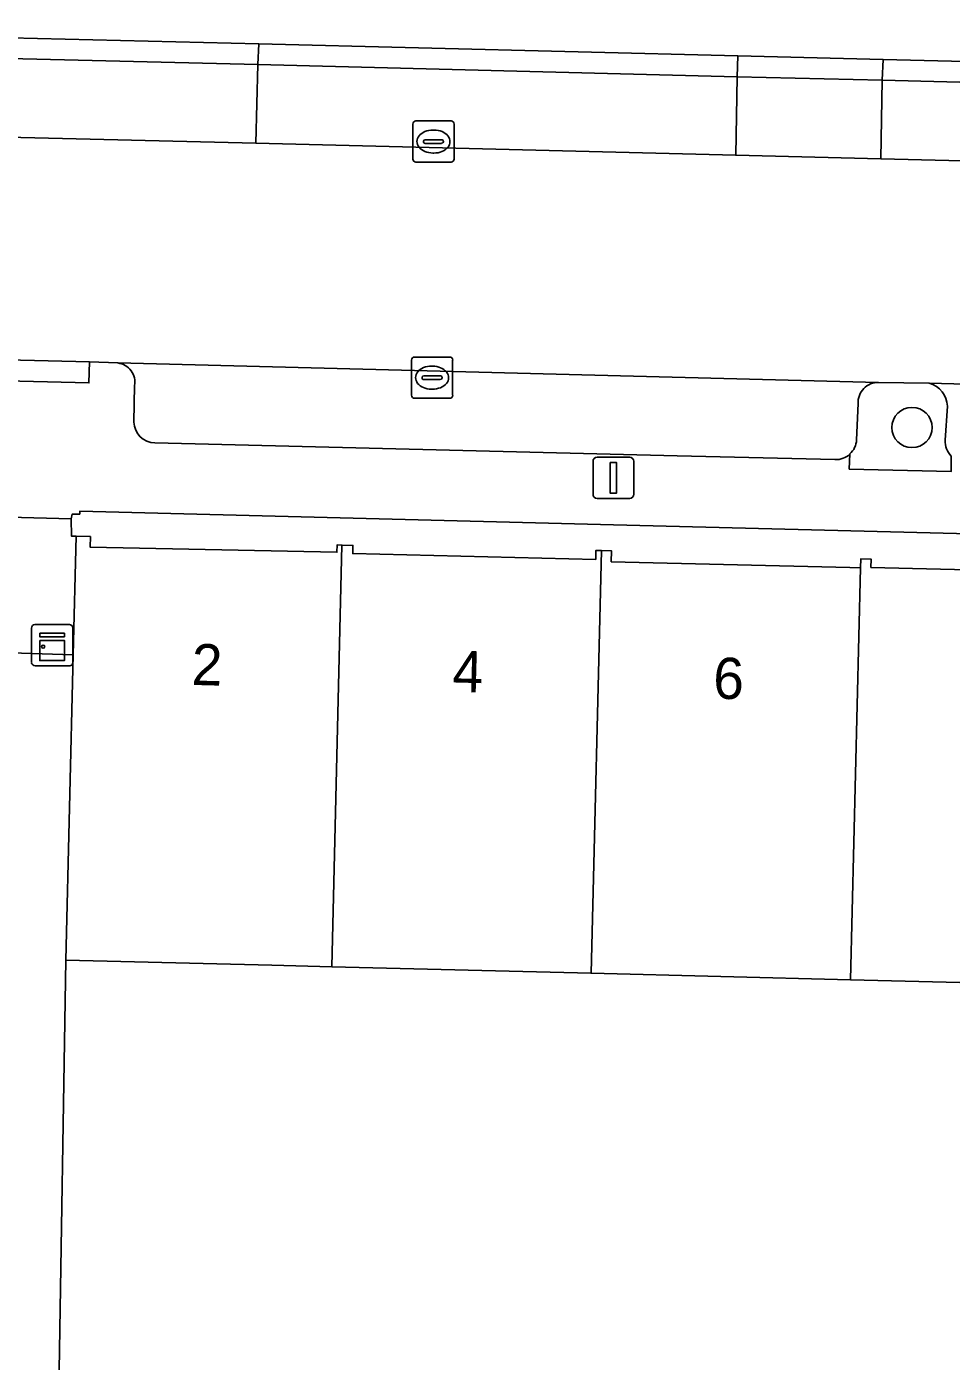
# Model space of a CAD drawing. Extents: x 162082 to 163401, y 388089 to 388636.
# Drawn here: x 162369.45 to 162391.89, y 388440.14 to 388472.55 of the extents above; entities that cross this region are included whole.
import ezdxf

# ---------------------------------------------------------------- set-up
doc = ezdxf.new("R2010")
doc.units = 0
for name, color, linetype in [('IMGEO_Berm_open', 7, 'Continuous'), ('IMGEO_Boom', 7, 'Continuous'), ('IMGEO_Erf', 7, 'Continuous'), ('IMGEO_Fietspad_gesloten', 7, 'Continuous'), ('IMGEO_Groenvoorziening', 7, 'Continuous'), ('IMGEO_Kast', 7, 'Continuous'), ('IMGEO_Kolk', 7, 'Continuous'), ('IMGEO_Lichtmast', 7, 'Continuous'), ('IMGEO_Pand', 7, 'Continuous'), ('IMGEO_Pand_nummerreeks', 7, 'Continuous'), ('IMGEO_Parkeervlak_open', 7, 'Continuous'), ('IMGEO_Rijbaan_lokaal_gesloten', 7, 'Continuous'), ('IMGEO_Rijbaan_lokaal_open', 7, 'Continuous'), ('IMGEO_Voetpad_open', 7, 'Continuous')]:
    doc.layers.add(name, color=color, linetype=linetype)

msp = doc.modelspace()

# ---------------------------------------------------------------- linework, layer by layer
at = {"layer": 'IMGEO_Berm_open'}
for points in [[(162386.708, 388471.847), (162375.078, 388472.135), (162375.054, 388471.636), (162386.691, 388471.334)], [(162401.837, 388471.472), (162390.238, 388471.759), (162390.215, 388471.253), (162401.824, 388470.956)]]:
    msp.add_lwpolyline(points, close=True, dxfattribs=at)
at = {"layer": 'IMGEO_Boom'}
msp.add_circle((162390.937, 388462.819), 0.489, dxfattribs=at)
at = {"layer": 'IMGEO_Erf'}
for points in [[(162433.966, 388459.183), (162383.691, 388460.456), (162370.734, 388460.784), (162370.734, 388460.717), (162370.655, 388460.714), (162370.546, 388460.711), (162370.521, 388460.602), (162370.536, 388460.18), (162370.644, 388460.18), (162370.99, 388460.172), (162370.984, 388459.916), (162376.976, 388459.791), (162376.982, 388459.966), (162377.097, 388459.963), (162377.365, 388459.957), (162377.36, 388459.757), (162383.26, 388459.614), (162383.265, 388459.833), (162383.396, 388459.83), (162383.643, 388459.824), (162383.636, 388459.56), (162389.43, 388459.416), (162389.687, 388459.409), (162389.692, 388459.628), (162389.944, 388459.622), (162389.939, 388459.421), (162395.682, 388459.278)], [(162433.427, 388437.851), (162433.687, 388448.306), (162427.233, 388448.467), (162420.935, 388448.623), (162420.878, 388446.285), (162418.504, 388446.407), (162418.62, 388448.681), (162414.638, 388448.78), (162408.34, 388448.937), (162402.042, 388449.094), (162395.743, 388449.25), (162389.445, 388449.407), (162383.147, 388449.564), (162376.849, 388449.721), (162375.393, 388449.757), (162370.394, 388449.881), (162370.224, 388439.424)]]:
    msp.add_lwpolyline(points, dxfattribs=at)
at = {"layer": 'IMGEO_Fietspad_gesloten'}
msp.add_lwpolyline([(162358.201, 388472.554), (162369.037, 388472.285), (162375.078, 388472.135), (162386.708, 388471.847), (162390.238, 388471.759), (162401.837, 388471.472), (162408.03, 388471.318), (162408.007, 388470.829), (162416.505, 388470.602), (162416.525, 388471.113), (162420.862, 388471.019), (162440.416, 388470.49), (162440.436, 388470.49), (162448.448, 388470.301), (162458.442, 388470.036), (162464.998, 388469.844), (162475.747, 388469.573), (162481.767, 388469.41), (162492.263, 388469.129), (162498.783, 388468.948), (162509.296, 388468.657)], dxfattribs=at)
at = {"layer": 'IMGEO_Groenvoorziening'}
for points in [[(162391.354, 388463.895), (162390.127, 388463.916)], [(162389.627, 388463.4), (162389.593, 388462.517)], [(162391.74, 388462.51), (162391.795, 388463.337)], [(162389.43, 388462.176), (162389.414, 388461.81), (162391.884, 388461.749), (162391.891, 388462.126)]]:
    msp.add_lwpolyline(points, dxfattribs=at)
for centre, radius, start, end in [((162390.122, 388463.42), 0.496, 89.4454, 182.359), ((162391.201, 388463.32), 0.595, 1.5906, 75.0496), ((162389.08, 388462.553), 0.514, 312.8768, 356.0271), ((162392.287, 388462.503), 0.547, 179.3135, 223.6188)]:
    msp.add_arc(centre, radius, start, end, dxfattribs=at)
at = {"layer": 'IMGEO_Kast'}
for p, q in [((162369.565, 388457.108), (162369.565, 388457.949)), ((162369.565, 388457.949), (162369.565, 388457.108)), ((162369.64, 388458.033), (162370.481, 388458.033)), ((162370.481, 388458.033), (162369.64, 388458.033)), ((162370.565, 388457.958), (162370.565, 388457.117)), ((162370.565, 388457.117), (162370.565, 388457.958)), ((162370.49, 388457.033), (162369.649, 388457.033)), ((162369.649, 388457.033), (162370.49, 388457.033))]:
    msp.add_line(p, q, dxfattribs=at)
for points in [[(162369.76, 388457.823), (162370.36, 388457.823), (162370.36, 388457.738), (162369.76, 388457.738), (162369.76, 388457.823)], [(162369.76, 388457.648), (162370.36, 388457.648), (162370.36, 388457.159), (162369.76, 388457.159), (162369.76, 388457.648)]]:
    msp.add_lwpolyline(points, dxfattribs=at)
msp.add_circle((162369.844, 388457.497), 0.0377, dxfattribs=at)
for centre, start, end in [((162369.643, 388457.955), 92.4484, 184.2845), ((162369.643, 388457.955), 92.4484, 184.2845), ((162370.487, 388457.955), 2.4484, 94.2845), ((162370.487, 388457.955), 2.4484, 94.2845), ((162369.643, 388457.111), 182.4484, 274.2845), ((162369.643, 388457.111), 182.4484, 274.2845), ((162370.487, 388457.111), 272.4484, 4.2845), ((162370.487, 388457.111), 272.4484, 4.2845)]:
    msp.add_arc(centre, 0.0779, start, end, dxfattribs=at)
at = {"layer": 'IMGEO_Kolk'}
for p, q in [((162378.894, 388470.264), (162379.746, 388470.264)), ((162378.819, 388469.338), (162378.819, 388470.19)), ((162379.307, 388470.044), (162379.332, 388470.044)), ((162379.82, 388470.19), (162379.82, 388469.338)), ((162379.078, 388469.758), (162379.078, 388469.77)), ((162379.516, 388469.721), (162379.118, 388469.721)), ((162379.121, 388469.807), (162379.519, 388469.807)), ((162379.562, 388469.77), (162379.562, 388469.758)), ((162379.746, 388469.264), (162378.894, 388469.264)), ((162379.33, 388469.484), (162379.305, 388469.484)), ((162378.785, 388463.604), (162378.785, 388464.456)), ((162378.86, 388464.53), (162379.712, 388464.53)), ((162379.786, 388464.456), (162379.786, 388463.604)), ((162379.087, 388464.073), (162379.485, 388464.073)), ((162379.273, 388464.31), (162379.298, 388464.31)), ((162379.044, 388464.024), (162379.044, 388464.036)), ((162379.482, 388463.987), (162379.084, 388463.987)), ((162379.296, 388463.75), (162379.271, 388463.75)), ((162379.528, 388464.036), (162379.528, 388464.024)), ((162379.712, 388463.53), (162378.86, 388463.53))]:
    msp.add_line(p, q, dxfattribs=at)
for points in [[(162378.894, 388470.264), (162379.746, 388470.264)], [(162378.819, 388469.338), (162378.819, 388470.19)], [(162379.82, 388470.19), (162379.82, 388469.338)], [(162379.746, 388469.264), (162378.894, 388469.264)], [(162378.785, 388463.604), (162378.785, 388464.456)], [(162378.86, 388464.53), (162379.712, 388464.53)], [(162379.786, 388464.456), (162379.786, 388463.604)], [(162379.712, 388463.53), (162378.86, 388463.53)]]:
    msp.add_lwpolyline(points, dxfattribs=at)
for centre, radius, start, end in [((162378.896, 388470.188), 0.0765, 91.552, 178.448), ((162378.896, 388470.188), 0.0765, 91.552, 178.448), ((162379.744, 388470.188), 0.0765, 1.552, 88.448), ((162379.744, 388470.188), 0.0765, 1.552, 88.448), ((162379.118, 388469.767), 0.0403, 85.8775, 175.7526), ((162379.115, 388469.757), 0.0366, 178.938, 274.7102), ((162379.519, 388469.764), 0.043, 264.8664, 352.4533), ((162379.523, 388469.769), 0.0386, 1.7309, 96.639), ((162378.896, 388469.34), 0.0765, 181.552, 268.448), ((162378.896, 388469.34), 0.0765, 181.552, 268.448), ((162379.744, 388469.34), 0.0765, 271.552, 358.448), ((162379.744, 388469.34), 0.0765, 271.552, 358.448), ((162378.862, 388464.454), 0.0765, 91.552, 178.448), ((162378.862, 388464.454), 0.0765, 91.552, 178.448), ((162379.71, 388464.454), 0.0765, 1.552, 88.448), ((162379.71, 388464.454), 0.0765, 1.552, 88.448), ((162379.084, 388464.033), 0.0403, 85.8775, 175.7526), ((162379.489, 388464.035), 0.0386, 1.7309, 96.639), ((162379.081, 388464.023), 0.0366, 178.938, 274.7102), ((162379.485, 388464.03), 0.043, 264.8664, 352.4533), ((162378.862, 388463.606), 0.0765, 181.552, 268.448), ((162378.862, 388463.606), 0.0765, 181.552, 268.448), ((162379.71, 388463.606), 0.0765, 271.552, 358.448), ((162379.71, 388463.606), 0.0765, 271.552, 358.448)]:
    msp.add_arc(centre, radius, start, end, dxfattribs=at)
for centre, major_axis, ratio, start_param, end_param in [((162379.306, 388469.764), (-0.387, 0.002), 0.722429, 4.712389, 7.853982), ((162379.331, 388469.764), (-0.39, 0.002), 0.717154, 1.570796, 4.712389), ((162379.272, 388464.03), (-0.387, 0.002), 0.722429, 4.712389, 7.853982), ((162379.297, 388464.03), (-0.39, 0.002), 0.717154, 1.570796, 4.712389)]:
    msp.add_ellipse(centre, major_axis=major_axis, ratio=ratio, start_param=start_param, end_param=end_param, dxfattribs=at)
at = {"layer": 'IMGEO_Lichtmast'}
for p, q in [((162383.193, 388461.198), (162383.193, 388461.998)), ((162383.193, 388461.998), (162383.193, 388461.198)), ((162383.293, 388462.098), (162384.083, 388462.098)), ((162384.083, 388462.098), (162383.293, 388462.098)), ((162384.183, 388461.998), (162384.183, 388461.198)), ((162384.183, 388461.198), (162384.183, 388461.998)), ((162384.083, 388461.098), (162383.293, 388461.098)), ((162383.293, 388461.098), (162384.083, 388461.098))]:
    msp.add_line(p, q, dxfattribs=at)
msp.add_lwpolyline([(162383.613, 388461.973), (162383.763, 388461.973), (162383.763, 388461.223), (162383.613, 388461.223), (162383.613, 388461.973)], dxfattribs=at)
for centre, start, end in [((162383.293, 388461.998), 90, 180), ((162383.293, 388461.998), 90, 180), ((162384.083, 388461.998), 0, 90), ((162384.083, 388461.998), 360, 90), ((162383.293, 388461.198), 180, 270), ((162383.293, 388461.198), 180, 270), ((162384.083, 388461.198), 270, 0), ((162384.083, 388461.198), 270, 0)]:
    msp.add_arc(centre, 0.1, start, end, dxfattribs=at)
at = {"layer": 'IMGEO_Pand'}
for points in [[(162376.849, 388449.721), (162377.097, 388459.963), (162376.982, 388459.966), (162376.976, 388459.791), (162370.984, 388459.916), (162370.99, 388460.172), (162370.644, 388460.18), (162370.574, 388457.3), (162370.394, 388449.881), (162375.393, 388449.757)], [(162383.396, 388459.83), (162383.265, 388459.833), (162383.26, 388459.614), (162377.36, 388459.757), (162377.365, 388459.957), (162377.097, 388459.963), (162376.849, 388449.721), (162383.147, 388449.564)], [(162389.687, 388459.409), (162389.43, 388459.416), (162383.636, 388459.56), (162383.643, 388459.824), (162383.396, 388459.83), (162383.147, 388449.564), (162389.445, 388449.407)], [(162395.986, 388459.271), (162395.682, 388459.278), (162389.939, 388459.421), (162389.944, 388459.622), (162389.692, 388459.628), (162389.687, 388459.409), (162389.445, 388449.407), (162395.743, 388449.25)]]:
    msp.add_lwpolyline(points, close=True, dxfattribs=at)
at = {"layer": 'IMGEO_Parkeervlak_open'}
msp.add_lwpolyline([(162386.691, 388471.334), (162375.054, 388471.636), (162375.01, 388469.723), (162386.66, 388469.431)], close=True, dxfattribs=at)
for points in [[(162401.824, 388470.956), (162390.215, 388471.253), (162390.18, 388469.346), (162402.728, 388469.034)], [(162390.127, 388463.916), (162371.659, 388464.386)], [(162372.065, 388463.838), (162372.047, 388462.949)], [(162420.621, 388463.13), (162408.184, 388463.445), (162391.354, 388463.895)], [(162389.593, 388462.517), (162389.627, 388463.4)], [(162391.795, 388463.337), (162391.74, 388462.51)], [(162372.557, 388462.447), (162385.239, 388462.134), (162389.067, 388462.04)]]:
    msp.add_lwpolyline(points, dxfattribs=at)
for centre, radius, start, end in [((162371.595, 388463.914), 0.477, 350.844, 82.2237), ((162390.122, 388463.42), 0.496, 89.4454, 182.359), ((162391.201, 388463.32), 0.595, 1.5906, 75.0496), ((162372.565, 388462.965), 0.518, 181.8053, 269.1005), ((162389.08, 388462.553), 0.514, 312.8768, 356.0271), ((162392.287, 388462.503), 0.547, 179.3135, 223.6188), ((162389.084, 388462.547), 0.508, 268.0986, 312.9789)]:
    msp.add_arc(centre, radius, start, end, dxfattribs=at)
at = {"layer": 'IMGEO_Rijbaan_lokaal_gesloten'}
for points in [[(162504.674, 388466.396), (162498.717, 388466.552), (162492.196, 388466.723), (162481.721, 388466.997), (162474.776, 388467.179), (162471.449, 388467.262), (162471.402, 388467.266), (162464.938, 388467.441), (162458.384, 388467.618), (162448.429, 388467.886), (162439.373, 388468.131), (162439.33, 388468.131), (162438.401, 388468.167), (162419.774, 388468.618), (162418.749, 388468.644), (162408.223, 388468.89), (162403.702, 388469.023), (162402.728, 388469.034), (162390.18, 388469.346), (162386.66, 388469.431), (162375.01, 388469.723), (162368.972, 388469.873), (162357.12, 388470.167), (162357.479, 388464.187)], [(162363.947, 388464.619), (162365.328, 388464.563), (162365.948, 388464.538), (162370.967, 388464.412), (162371.659, 388464.386), (162390.127, 388463.916), (162391.354, 388463.895), (162408.184, 388463.445), (162420.621, 388463.13), (162421.807, 388463.11), (162462.126, 388462.081), (162463.206, 388462.062), (162475.436, 388461.725), (162497.037, 388461.139)]]:
    msp.add_lwpolyline(points, dxfattribs=at)
at = {"layer": 'IMGEO_Rijbaan_lokaal_open'}
msp.add_lwpolyline([(162370.644, 388460.18), (162370.536, 388460.18), (162370.521, 388460.602), (162366.001, 388460.726), (162365.975, 388460.578), (162365.87, 388459.93), (162365.799, 388457.454), (162370.574, 388457.3)], close=True, dxfattribs=at)
msp.add_lwpolyline([(162370.224, 388439.424), (162370.394, 388449.881), (162370.574, 388457.3), (162365.799, 388457.454)], dxfattribs=at)
at = {"layer": 'IMGEO_Voetpad_open'}
for points in [[(162375.078, 388472.135), (162369.037, 388472.285), (162369.02, 388471.78), (162375.054, 388471.636)], [(162390.238, 388471.759), (162386.708, 388471.847), (162386.691, 388471.334), (162390.215, 388471.253)], [(162375.054, 388471.636), (162369.02, 388471.78), (162368.972, 388469.873), (162375.01, 388469.723)], [(162390.215, 388471.253), (162386.691, 388471.334), (162386.66, 388469.431), (162390.18, 388469.346)], [(162370.967, 388464.412), (162365.948, 388464.538), (162365.916, 388464.025), (162370.954, 388463.902)]]:
    msp.add_lwpolyline(points, close=True, dxfattribs=at)
for points in [[(162371.659, 388464.386), (162370.967, 388464.412), (162370.954, 388463.902), (162365.916, 388464.025), (162365.948, 388464.538), (162365.328, 388464.563), (162365.27, 388462.394), (162359.684, 388462.54), (162359.741, 388464.48), (162359.611, 388464.465)], [(162372.047, 388462.949), (162372.065, 388463.838)], [(162389.067, 388462.04), (162385.239, 388462.134), (162372.557, 388462.447)], [(162391.891, 388462.126), (162391.884, 388461.749), (162389.414, 388461.81), (162389.43, 388462.176)], [(162348.465, 388460.809), (162349.16, 388459.748), (162344.51, 388456.617), (162345.699, 388455.235), (162350.246, 388458.32), (162358.756, 388460.74), (162365.975, 388460.578), (162366.001, 388460.726), (162370.521, 388460.602), (162370.546, 388460.711), (162370.655, 388460.714), (162370.734, 388460.717), (162370.734, 388460.784), (162383.691, 388460.456), (162433.966, 388459.183), (162434.894, 388459.159), (162435.462, 388459.144), (162475.598, 388458.096), (162498.856, 388457.469), (162500.341, 388457.43), (162525.566, 388456.776)]]:
    msp.add_lwpolyline(points, dxfattribs=at)
for centre, radius, start, end in [((162371.595, 388463.914), 0.477, 350.844, 82.2237), ((162372.565, 388462.965), 0.518, 181.8053, 269.1005), ((162389.084, 388462.547), 0.508, 268.0986, 312.9789)]:
    msp.add_arc(centre, radius, start, end, dxfattribs=at)

# ---------------------------------------------------------------- texts
at = {"layer": 'IMGEO_Pand_nummerreeks'}
for s, rotation, p in [('2', 358.4993, (162373.44, 388456.568)), ('4', 358.4993, (162379.771, 388456.402)), ('6', 358.4989, (162386.102, 388456.237))]:
    msp.add_text(s, height=1, rotation=rotation, dxfattribs=at).set_placement(p)

doc.saveas('drawing.dxf')
